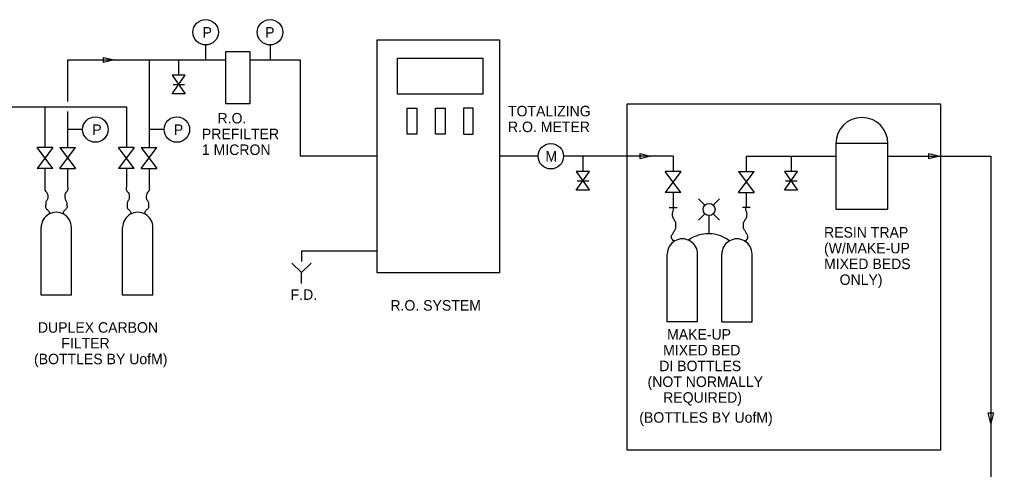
# Model space of a CAD drawing. Extents: x 9934 to 10051, y 10032 to 10115.
# Drawn here: x 9982.7 to 10044.6, y 10086.2 to 10114.7 of the extents above; entities that cross this region are included whole.
import ezdxf

# ---------------------------------------------------------------- set-up
doc = ezdxf.new("R2010")
doc.units = 0
doc.layers.add('G-ANNO-TEXT', color=7, linetype='Continuous')
doc.layers.add('M-STEM-CONP', color=7, linetype='Continuous')

msp = doc.modelspace()

# ---------------------------------------------------------------- linework, layer by layer
at = {"layer": 'G-ANNO-TEXT'}
for p, q in [((9994.567, 10113.089), (9994.567, 10112.136)), ((9998.654, 10113.089), (9998.654, 10112.136)), ((9986.758, 10107.724), (9985.805, 10107.724)), ((9991.933, 10107.724), (9990.979, 10107.724)), ((10034.575, 10106.831), (10034.575, 10102.665)), ((10037.886, 10106.831), (10034.575, 10106.831)), ((10037.886, 10102.665), (10037.886, 10106.831)), ((10034.575, 10102.665), (10037.886, 10102.665)), ((9984.124, 10097.217), (9984.124, 10101.516)), ((9986.046, 10097.217), (9986.046, 10101.516)), ((9989.299, 10097.217), (9989.299, 10101.516)), ((9991.221, 10097.217), (9991.221, 10101.516)), ((10005.452, 10100.008), (10000.653, 10100.008)), ((10000.653, 10100.008), (10000.653, 10099.35)), ((10023.875, 10095.526), (10023.875, 10099.826)), ((10025.797, 10095.526), (10025.797, 10099.826)), ((10027.338, 10095.526), (10027.338, 10099.826)), ((10029.26, 10095.526), (10029.26, 10099.826)), ((10000.653, 10098.648), (10000.049, 10099.251)), ((10000.653, 10098.648), (10001.257, 10099.251)), ((10000.653, 10097.949), (10000.653, 10098.648)), ((9986.046, 10097.217), (9984.124, 10097.217)), ((9991.221, 10097.217), (9989.299, 10097.217)), ((10025.797, 10095.526), (10023.875, 10095.526)), ((10027.338, 10095.526), (10029.26, 10095.526))]:
    msp.add_line(p, q, dxfattribs=at)
for points in [[(10005.46, 10113.422), (10013.222, 10113.422), (10013.222, 10098.638), (10005.46, 10098.638)], [(9995.855, 10112.677), (9997.366, 10112.677), (9997.366, 10109.345), (9995.855, 10109.345)], [(10006.753, 10112.252), (10012.174, 10112.252), (10012.174, 10109.972), (10006.753, 10109.972)], [(10007.367, 10109.088), (10007.983, 10109.088), (10007.983, 10107.425), (10007.367, 10107.425)], [(10009.156, 10109.088), (10009.772, 10109.088), (10009.772, 10107.425), (10009.156, 10107.425)], [(10011.561, 10109.088), (10010.945, 10109.088), (10010.945, 10107.425), (10011.561, 10107.425)], [(10021.325, 10109.347), (10041.223, 10109.347), (10041.223, 10087.391), (10021.325, 10087.391)]]:
    msp.add_lwpolyline(points, close=True, dxfattribs=at)
for centre in [(9994.567, 10113.897), (9998.654, 10113.897), (9987.567, 10107.724), (9992.741, 10107.724), (10016.481, 10106.03)]:
    msp.add_circle(centre, 0.808, dxfattribs=at)
for centre, radius, start, end in [((10036.231, 10106.831), 1.656, 0, 180), ((9985.085, 10101.516), 0.961, 0, 180.00009), ((9990.26, 10101.516), 0.961, 0, 180.00009), ((10024.836, 10099.826), 0.961, 0, 180.00009), ((10028.299, 10099.826), 0.961, 359.99991, 180)]:
    msp.add_arc(centre, radius, start, end, dxfattribs=at)
at = {"layer": 'M-STEM-CONP'}
for p, q in [((9985.805, 10112.136), (9985.805, 10109.504)), ((9985.805, 10112.136), (9995.855, 10112.136)), ((9990.979, 10112.136), (9990.979, 10106.582)), ((9992.851, 10112.136), (9992.851, 10111.171)), ((9997.366, 10112.136), (10000.558, 10112.136)), ((10000.558, 10112.136), (10000.558, 10106.03)), ((9993.268, 10111.171), (9992.434, 10111.171)), ((9992.434, 10111.171), (9993.268, 10109.981)), ((9992.434, 10109.981), (9993.268, 10111.171)), ((9992.501, 10110.576), (9993.231, 10110.576)), ((9993.268, 10109.981), (9992.434, 10109.981)), ((9977.116, 10109.162), (9989.54, 10109.162)), ((9984.365, 10109.162), (9984.365, 10106.582)), ((9985.805, 10108.866), (9985.805, 10106.582)), ((9989.54, 10109.162), (9989.54, 10106.582)), ((9984.865, 10106.582), (9983.865, 10106.582)), ((9984.865, 10106.582), (9983.865, 10105.249)), ((9984.865, 10105.249), (9983.865, 10106.582)), ((9985.305, 10106.582), (9986.305, 10106.582)), ((9985.305, 10106.582), (9986.305, 10105.249)), ((9985.305, 10105.249), (9986.305, 10106.582)), ((9990.04, 10106.582), (9989.04, 10106.582)), ((9990.04, 10106.582), (9989.04, 10105.249)), ((9990.04, 10105.249), (9989.04, 10106.582)), ((9990.479, 10106.582), (9991.479, 10106.582)), ((9990.479, 10106.582), (9991.479, 10105.249)), ((9990.479, 10105.249), (9991.479, 10106.582)), ((10005.46, 10106.03), (10000.558, 10106.03)), ((10015.672, 10106.03), (10013.222, 10106.03)), ((10024.243, 10106.03), (10017.289, 10106.03)), ((10018.514, 10106.03), (10018.514, 10105.066)), ((10024.243, 10106.03), (10024.243, 10105.066)), ((10028.891, 10106.03), (10028.891, 10105.066)), ((10028.891, 10106.03), (10034.575, 10106.03)), ((10031.733, 10106.03), (10031.733, 10105.066)), ((10037.886, 10106.03), (10044.42, 10106.03)), ((10044.42, 10106.03), (10044.42, 10075.384)), ((9984.865, 10105.249), (9983.865, 10105.249)), ((9984.365, 10105.249), (9984.365, 10104.288)), ((9985.305, 10105.249), (9986.305, 10105.249)), ((9985.805, 10105.249), (9985.805, 10104.288)), ((9990.04, 10105.249), (9989.04, 10105.249)), ((9989.54, 10105.249), (9989.54, 10104.288)), ((9990.479, 10105.249), (9991.479, 10105.249)), ((9990.979, 10105.249), (9990.979, 10104.288)), ((10018.931, 10105.066), (10018.097, 10105.066)), ((10018.097, 10105.066), (10018.931, 10103.875)), ((10018.097, 10103.875), (10018.931, 10105.066)), ((10024.743, 10105.066), (10023.743, 10105.066)), ((10024.743, 10105.066), (10023.743, 10103.732)), ((10024.743, 10103.732), (10023.743, 10105.066)), ((10028.391, 10105.066), (10029.391, 10105.066)), ((10028.391, 10105.066), (10029.391, 10103.732)), ((10028.391, 10103.732), (10029.391, 10105.066)), ((10032.15, 10105.066), (10031.316, 10105.066)), ((10031.316, 10105.066), (10032.15, 10103.875)), ((10031.316, 10103.875), (10032.15, 10105.066)), ((10018.164, 10104.471), (10018.894, 10104.471)), ((10031.383, 10104.471), (10032.113, 10104.471)), ((10018.931, 10103.875), (10018.097, 10103.875)), ((10032.15, 10103.875), (10031.316, 10103.875)), ((10024.743, 10103.732), (10023.743, 10103.732)), ((10024.243, 10103.732), (10024.243, 10102.772)), ((10026.256, 10102.921), (10025.858, 10103.319)), ((10026.797, 10102.921), (10027.195, 10103.319)), ((10028.391, 10103.732), (10029.391, 10103.732)), ((10028.891, 10103.732), (10028.891, 10102.772)), ((10023.993, 10102.772), (10024.493, 10102.772)), ((10029.141, 10102.772), (10028.641, 10102.772)), ((10025.858, 10101.982), (10026.256, 10102.38)), ((10026.527, 10101.113), (10026.527, 10102.268)), ((10027.195, 10101.982), (10026.797, 10102.38))]:
    msp.add_line(p, q, dxfattribs=at)
for points in [[(9988.086, 10112.302), (9988.753, 10112.136), (9988.086, 10111.969)], [(10022.153, 10106.197), (10022.819, 10106.03), (10022.153, 10105.863)], [(10040.487, 10106.197), (10041.153, 10106.03), (10040.487, 10105.863)], [(10044.587, 10089.744), (10044.42, 10089.077), (10044.254, 10089.744)]]:
    msp.add_lwpolyline(points, close=True, dxfattribs=at)
msp.add_circle((10026.527, 10102.65), 0.383, dxfattribs=at)
msp.add_arc((10026.485, 10098.958), 2.155, 51.94588, 125.83187, dxfattribs=at)
for points in [[(9984.363, 10104.27), (9984.363, 10104.07), (9984.363, 10103.87), (9984.513, 10103.671), (9984.546, 10103.488), (9984.529, 10103.305), (9984.43, 10103.138), (9984.413, 10102.955), (9984.413, 10102.755), (9984.546, 10102.606), (9984.646, 10102.456), (9984.663, 10102.389)], [(9985.807, 10104.27), (9985.807, 10104.07), (9985.807, 10103.87), (9985.657, 10103.671), (9985.624, 10103.488), (9985.641, 10103.305), (9985.741, 10103.138), (9985.757, 10102.955), (9985.757, 10102.755), (9985.624, 10102.606), (9985.524, 10102.456), (9985.508, 10102.389)], [(9989.537, 10104.27), (9989.537, 10104.07), (9989.537, 10103.87), (9989.687, 10103.671), (9989.72, 10103.488), (9989.704, 10103.305), (9989.604, 10103.138), (9989.587, 10102.955), (9989.587, 10102.755), (9989.72, 10102.606), (9989.82, 10102.456), (9989.837, 10102.389)], [(9990.982, 10104.27), (9990.982, 10104.07), (9990.982, 10103.87), (9990.832, 10103.671), (9990.799, 10103.488), (9990.815, 10103.305), (9990.915, 10103.138), (9990.932, 10102.955), (9990.932, 10102.755), (9990.799, 10102.606), (9990.699, 10102.456), (9990.682, 10102.389)], [(10024.313, 10100.635), (10024.206, 10100.742), (10024.147, 10100.979), (10024.236, 10101.128), (10024.325, 10101.305), (10024.413, 10101.453), (10024.413, 10101.631), (10024.413, 10101.809), (10024.295, 10102.016), (10024.206, 10102.253), (10024.206, 10102.431), (10024.265, 10102.609), (10024.243, 10102.772)], [(10028.822, 10100.635), (10028.929, 10100.742), (10028.988, 10100.979), (10028.899, 10101.128), (10028.81, 10101.305), (10028.721, 10101.453), (10028.721, 10101.631), (10028.721, 10101.809), (10028.84, 10102.016), (10028.929, 10102.253), (10028.929, 10102.431), (10028.87, 10102.609), (10028.891, 10102.772)]]:
    msp.add_spline(points, degree=3, dxfattribs=at)

# ---------------------------------------------------------------- texts
at = {"layer": 'G-ANNO-TEXT'}
for s, height, p in [('P', 0.667, (9994.371, 10113.556)), ('P', 0.667, (9998.344, 10113.556)), ('    R.O.', 0.6667, (9994.33, 10108.11)), ('TOTALIZING', 0.6667, (10013.763, 10108.56)), ('R.O. METER', 0.6667, (10013.763, 10107.56)), ('P', 0.667, (9987.371, 10107.382)), ('P', 0.667, (9992.545, 10107.382)), ('PREFILTER', 0.6667, (9994.33, 10107.11)), ('1 MICRON', 0.6667, (9994.33, 10106.11)), ('RESIN TRAP', 0.6667, (10033.826, 10100.868)), ('(W/MAKE-UP', 0.6667, (10033.826, 10099.868)), ('MIXED BEDS', 0.6667, (10033.826, 10098.868)), ('    ONLY)', 0.6667, (10033.826, 10097.868)), ('F.D.', 0.6667, (9999.962, 10096.917)), ('R.O. SYSTEM', 0.66667, (10006.297, 10096.234)), (' DUPLEX CARBON', 0.66667, (9983.671, 10094.833)), ('     MAKE-UP', 0.66667, (10022.623, 10094.392)), ('       FILTER', 0.66667, (9983.671, 10093.833)), ('    MIXED BED', 0.66667, (10022.623, 10093.392)), ('(BOTTLES BY UofM)', 0.66667, (9983.671, 10092.833)), ('   DI BOTTLES', 0.66667, (10022.623, 10092.392)), ('(NOT NORMALLY', 0.66667, (10022.623, 10091.392)), ('    REQUIRED)', 0.66667, (10022.623, 10090.392)), ('(BOTTLES BY UofM)', 0.66667, (10022.098, 10089.123))]:
    msp.add_text(s, height=height, dxfattribs=at).set_placement(p)
msp.add_text('M', height=0.667, rotation=360, dxfattribs=at).set_placement((10016.14, 10105.688))

doc.saveas('drawing.dxf')
